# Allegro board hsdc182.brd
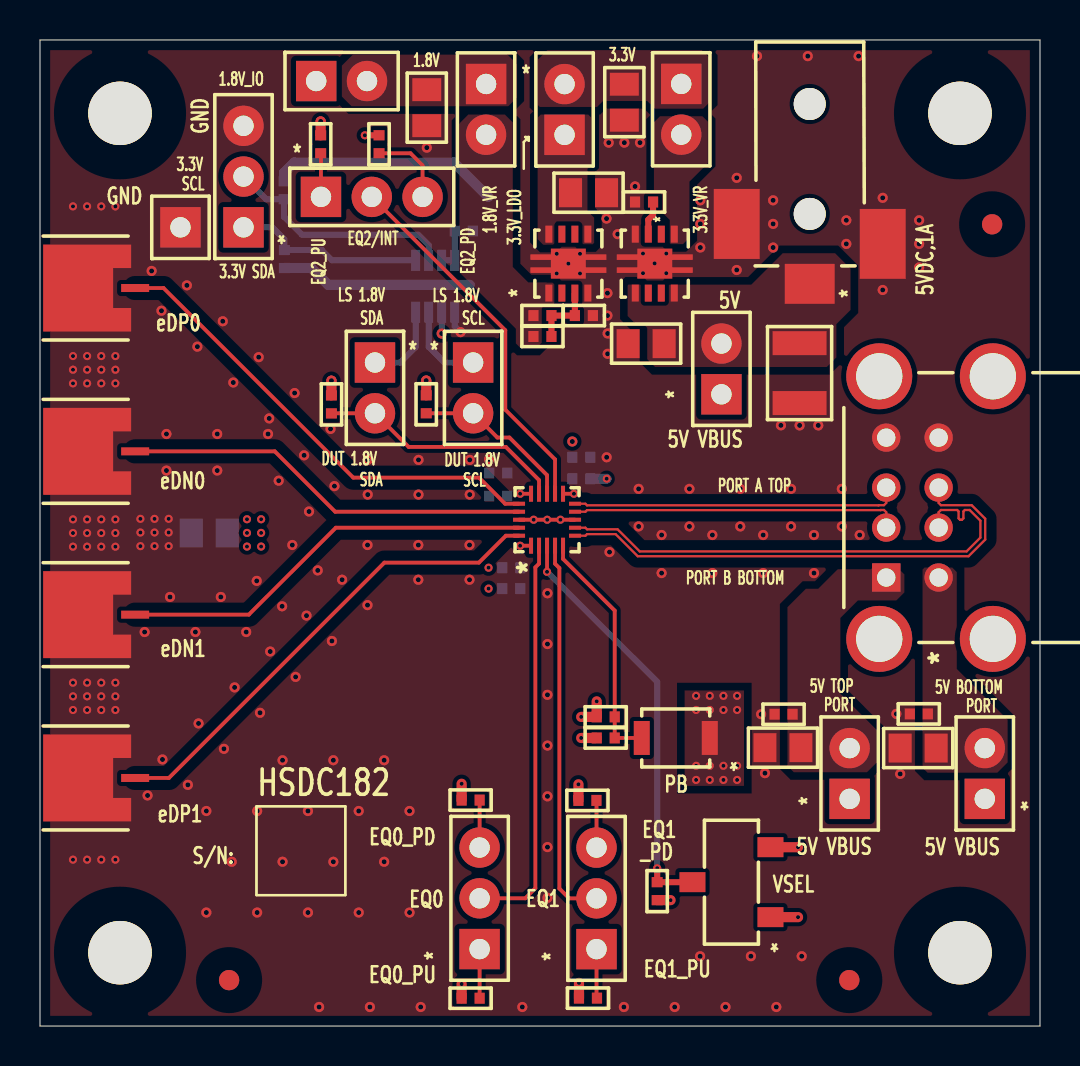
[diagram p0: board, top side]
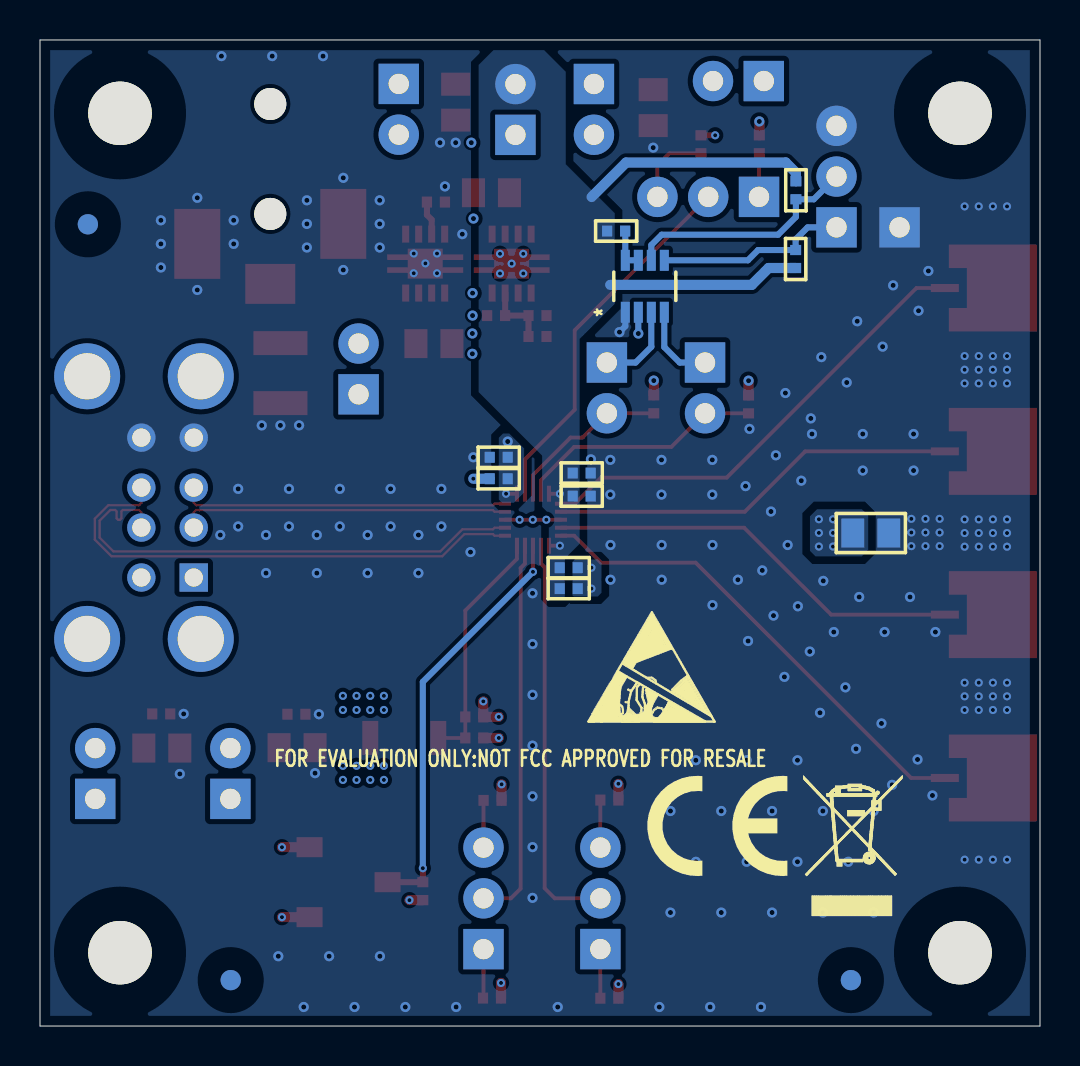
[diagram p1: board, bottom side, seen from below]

Outline 50 x 49.34 mm; copper layers: TOP, L2, L3, BOTTOM. Coordinates in mm from the lower left corner of the outline.
Outline path: 0,49.34 50,49.34 50,0 0,0 0,49.34

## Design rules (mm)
constraint set DEFAULT: min track width 0.191
net group 1.8V_IO: nets N16778222 N16778248 N16778386 N16778440 N16778562 N16778631 R_SCL R_SDA RESETB/ VIOSEL
net group CLS1: nets DNA DNB DPA DPB EDN0_1 EDN1_1 EDP0_1 EDP1_1
net group N16778948: nets N16779025

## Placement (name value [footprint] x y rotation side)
C1  47uF  [CAP_1210]  37.98 32.67 270 top
C2  .1uF  [CAP_0402]  27.07 27.39 0 bottom
C3  .1uF  [CAP_0402]  27.07 28.46 0 bottom
C4  2.2uF  [CAP_0805]  37.15 13.93 180 top
C5  .1uF  [CAP_0402]  37.18 15.6 180 top
C6  .1uF  [CAP_0402]  43.94 15.62 180 top
C7  2.2uF  [CAP_0805]  43.91 13.91 180 top
C8  .01uF  [CAP_0402]  22.92 26.52 180 bottom
C9  .01uF  [CAP_0402]  23.57 21.89 180 bottom
C10  .1uF  [CAP_0402]  22.92 27.67 180 bottom
C11  .1uF  [CAP_0402]  23.57 22.93 180 bottom
C12  .1uF  [CAP_0402]  30.86 6.75 270 top
C13  .1uF  [CAP_0402]  28.29 15.47 180 top
C14  1uF  [CAP_0805]  30.31 34.15 180 top
C15  10uF  [CAP_0805]  29.22 46.23 270 top
C16  1uF  [CAP_0805]  27.43 41.7 0 top
C17  .01uF  [CAP_0402]  25.12 34.5 0 top
C18  10uF  [CAP_0805]  19.34 45.95 270 top
C19  .01uF  [CAP_0402]  30.2 41.23 180 top
J1  DC JACK  [JACK_SMRT_PJ1-022-SMT-TR]  38.49 43.59 90 top
J2  HDR2X1  [HDR_THVT_1X2_254_871]  34.07 31.61 90 top
J3  HDR2X1  [HDR_THVT_1X2_254_871]  40.48 11.37 90 top
J4  TypeA Stacked  [USB-A_THRT_AU-Y1008-2]  47.64 25.94 90 top
J5  HDR3X1  [HDR_THVT_1X3_254_871]  27.83 3.85 90 top
J6  SMP  [CON_SMRT_19S201-40ML5]  2.81 36.93 270 top
J7  SMP  [CON_SMRT_19S201-40ML5]  2.81 28.76 270 top
J8  SMP  [CON_SMRT_19S201-40ML5]  2.81 20.58 270 top
J9  SMP  [CON_SMRT_19S201-40ML5]  2.81 12.41 270 top
J10  HDR2X1  [HDR_THVT_1X2_254_871]  47.24 11.37 90 top
J11  HDR3X1  [HDR_THVT_1X3_254_871]  21.98 3.85 90 top
J12  HDR3X1  [HDR_THVT_1X3_254_871]  14.05 41.49 0 top
J13  HDR2X1  [HDR_THVT_1X2_254_871]  13.81 47.28 0 top
J14  HDR2X1  [HDR_THVT_1X2_254_871]  32.06 47.14 270 top
J15  HDR2X1  [HDR_THVT_1X2_254_871]  26.23 44.59 90 top
J16  HDR2X1  [HDR_THVT_1X2_254_871]  22.3 47.14 270 top
J17  HDR2X1  [HDR_THVT_1X2_254_871]  16.75 33.2 270 top
J18  HDR2X1  [HDR_THVT_1X2_254_871]  21.66 33.2 270 top
J19  HDR3X1  [HDR_THVT_1X3_254_871]  10.18 39.96 90 top
NOREF  -  []  0 49.34 0 top
NOREF#2  -  [unnamed#2]  4 45.67 0 top
NOREF#3  -  [unnamed#2]  46 3.67 0 top
NOREF#4  -  []  8.59 6.2 0 top
NOREF#5  -  []  0 0 0 top
NOREF#6  -  []  -18.79 5.95 0 top
NOREF#7  -  [unnamed#2]  9.45 2.3 0 top
NOREF#8  -  [unnamed#2]  4 3.67 0 top
NOREF#9  -  [unnamed#2]  47.61 40.12 0 top
NOREF#10  -  []  4 45.67 0 top
NOREF#11  -  []  88.9 38.1 0 top
NOREF#12  -  [unnamed#2]  46 45.67 0 top
NOREF#13  -  []  50 0 90 top
NOREF#14  -  []  46 3.67 90 top
NOREF#15  -  [unnamed#2]  40.46 2.3 0 top
NOREF#16  -  []  -3.81 -69.85 0 top
NOREF#17  -  [unnamed#2]  40.46 2.3 180 bottom
NOREF#18  -  []  17.14 16.39 180 bottom
NOREF#19  -  [unnamed#2]  9.45 2.3 180 bottom
NOREF#20  -  []  16.13 10.01 180 bottom
NOREF#21  -  [unnamed#2]  47.61 40.12 180 bottom
R1  10K  [RES_0402]  27.4 1.4 0 top
R2  10K  [RES_0402]  27.37 11.29 180 top
R3  10K  [RES_0402]  21.53 1.39 0 top
R4  10K  [RES_0402]  21.53 11.31 180 top
R5  10K  [RES_0402]  14.03 44.12 270 top
R6  2.2K  [RES_0402]  28.29 14.41 0 top
R7  10K  [RES_0402]  16.95 44.12 90 top
R8  28.0K  [RES_0402]  25.12 35.55 0 top
R9  56.2K  [RES_0402]  27.19 35.55 0 top
R10  0  [RES_0805]  8.46 24.67 180 bottom
R11  200K  [RES_0402]  21.19 39.78 0 bottom
R12  1K  [RES_0402]  14.57 31.1 270 top
R13  1K  [RES_0402]  19.31 31.11 270 top
R14  4.7K  [RES_0402]  12.22 38.38 270 bottom
R15  4.7K  [RES_0402]  12.2 41.82 90 bottom
SW1  Switch  [SW_SMVT_CJS-1201B]  34.57 7.2 180 top
SW2  RESETB  [SW_SMVT_B3U-1000P]  31.79 14.41 180 top
TP1  TEST POINT  [HDR_THVT_1X1_871]  7.02 39.96 90 top
U1  TUSB2E221QFN  [VBW0020A]  25.35 25.33 90 top
U2  TPS73633 DRB  [DRB0008BA_150X175]  30.74 38.15 270 top
U3  TPS73601 DRB  [DRB0008BA_150X175]  26.42 38.15 90 top
U4  TCA39306DDFR  [DDF0008A]  19.76 37.02 90 bottom

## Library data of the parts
C1 = CAPACITOR POL: signal model: DEFAULT_CAPACITOR_4.7e+07pF_1_2
C2 C3 C5 C6 C10-C13 = CAP NP: signal model: DEFAULT_CAPACITOR_100000pF_1_2
C4 C7 = CAPACITOR POL: signal model: DEFAULT_CAPACITOR_2.2e+06pF_1_2
C8 C9 C17 C19 = CAP NP: signal model: DEFAULT_CAPACITOR_10000pF_1_2
C14 C16 = CAP NP: signal model: DEFAULT_CAPACITOR_1e+06pF_1_2
C15 C18 = CAP NP: signal model: DEFAULT_CAPACITOR_1e+07pF_1_2
J1 = PWR JACK
J2 J3 J10 J13-J18 = HDR2X1 M .1
J4 = AU-Y1008-2_0
J5 J11 J12 J19 = HDR3X1 M .1
J6-J9 = SMB_0
R1-R5 R7 = RES: signal model: DEFAULT_RESISTOR_10000OHM_1_2
R6 = RES: signal model: DEFAULT_RESISTOR_2200OHM_1_2
R8 = RES: signal model: DEFAULT_RESISTOR_28000OHM_1_2
R9 = RES: signal model: DEFAULT_RESISTOR_56200OHM_1_2
R10 = RES: signal model: DEFAULT_RESISTOR_0.001OHM_1_2
R11 = SG73P1ETTP2003D
R12 R13 = RES: signal model: DEFAULT_RESISTOR_1000.000000OHM_1_2
R14 R15 = RC0402JR-074K7L
SW1 = Switch CJS-1201
SW2 = SW KEY-SPST
TP1 = Test Point Small
U1 = TUSB2E221QFN
U2 = TPS736_DRB_3
U3 = TPS736_DRB_4
U4 = TCA39306DDFR_0

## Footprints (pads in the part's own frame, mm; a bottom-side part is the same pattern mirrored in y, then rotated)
CAP_0402
  rect 0.51x0.55 smd: 1(-0.45,0) 2(0.45,0)
CAP_0805
  rect 1.15x1.45 smd: 1(-0.9,0) 2(0.9,0)
CAP_1210
  rect 1.2x2.7 smd: 1(-1.5,0) 2(1.5,0)
CON_SMRT_19S201-40ML5
  rect 0.4x1.4 smd: 1(0,1.95)
  custom 1.088x1.088 smd: 2(0,-0.45)
DDF0008A
  rect 1.05x0.45 smd: 1(-1.3,0.975) 2(-1.3,0.325) 3(-1.3,-0.325) 4(-1.3,-0.975) 5(1.3,-0.975) 6(1.3,-0.325) 7(1.3,0.325) 8(1.3,0.975)
DRB0008BA_150X175
  rect 0.85x0.35 smd: 1(-1.475,0.975) 2(-1.475,0.325) 3(-1.475,-0.325) 4(-1.475,-0.975) 5(1.475,-0.975) 6(1.475,-0.325) 7(1.475,0.325) 8(1.475,0.975)
  custom 0.375x0.375 smd: 9(0,0)
HDR_THVT_1X1_871
  rect 2.02x2.02 hole 1.02: 1(0,0)
HDR_THVT_1X2_254_871
  rect 2.02x2.02 hole 1.02: 1(0,0)
  round 2.02 hole 1.02: 2(2.54,0)
HDR_THVT_1X3_254_871
  rect 2.02x2.02 hole 1.02: 1(0,0)
  round 2.02 hole 1.02: 2(2.54,0) 3(5.08,0)
JACK_SMRT_PJ1-022-SMT-TR
  round 1.6 hole 1.6 unplated: (-2.95,0) (2.55,0)
  rect 2x2.5 smd: 1(-6.45,0)
  rect 3.5x2.3 smd: 2(-3.45,3.65) 3(-4.45,-3.65)
RES_0402
  rect 0.51x0.55 smd: 1(-0.45,0) 2(0.45,0)
RES_0805
  rect 1.15x1.45 smd: 1(-0.9,0) 2(0.9,0)
SW_SMVT_B3U-1000P
  rect 0.8x1.7 smd: 1(-1.7,0) 2(1.7,0)
SW_SMVT_CJS-1201B
  rect 1.3x1 smd: 1(-1.95,1.75) 2(1.95,0) 3(-1.95,-1.75)
unnamed#2
  round 3.175 hole 3.175 unplated: (0,0)
USB-A_THRT_AU-Y1008-2
  rect 1.42x1.42 hole 0.914: 1(-3.5,5.33)
  round 1.42 hole 0.914: 2(-1,5.33) 3(1,5.33) 4(3.5,5.33) 5(-3.5,2.71) 6(-1,2.71) 7(1,2.71) 8(3.5,2.71)
  round 3.3 hole 2.311: 9(-6.57,0) 10(6.57,0) 11(-6.57,5.68) 12(6.57,5.68)
VBW0020A
  rect 0.8x0.2 smd: 1(-1.3,0.8) 2(-1.3,0.4) 3(-1.3,0) 4(-1.3,-0.4) 5(-1.3,-0.8) 11(1.3,-0.8) 12(1.3,-0.4) 13(1.3,0) 14(1.3,0.4) 15(1.3,0.8)
  rect 0.2x0.6 smd: 6(-0.8,-1.4) 7(-0.4,-1.4) 8(0,-1.4) 9(0.4,-1.4) 10(0.8,-1.4) 16(0.8,1.4) 17(0.4,1.4) 18(0,1.4) 19(-0.4,1.4) 20(-0.8,1.4)

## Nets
1.8V: C2.1 C3.1 C18.1 J13.2 J16.1 SW1.3 U1.11
1.8V_IO: J13.1 R1.1 R3.1 R5.1 R6.1 R12.1 R13.1 U4.2
3.3V: C8.1 C9.1 C10.1 C11.1 C15.1 J14.1 J15.2 R11.2 R14.2 R15.2 U1.1 U1.15
3.3V_LDO: C16.1 J15.1 U3.5 U3.8
5V: C1.1 C14.1 J1.1(T) J2.2 U2.5 U2.8
5V VBUS: J2.1 J3.1 J10.1
5V_J1: C4.1 C5.1 J3.2 J4.1
5V_J2: C6.1 C7.1 J4.5 J10.2
GND: C1.2 C3.2 C4.2 C5.2 C6.2 C7.2 C8.2 C10.2 C14.2 C15.2 C16.2 C18.2 C19.2 J1.2 J1.3 J4.4 J4.8 J6.2 J7.2 J8.2 J9.2 J19.3 R9.2 R10.2 TP1.1(TP) U2.4 U2.9 U3.4 U3.9 U4.1
GND_SIGNAL: C2.2 C9.2 C11.2 C12.2 C13.2 R2.2 R4.2 R7.2 R10.1 SW1.1 SW2.1 U1.8 U1.18
DNA: J4.2 U1.9
DNB: J4.6 U1.7
DPA: J4.3 U1.10
DPB: J4.7 U1.6
EDN0_1: J7.1(CENTER) U1.17
EDN1_1: J8.1(CENTER) U1.19
EDP0_1: J6.1(CENTER) U1.16
EDP1_1: J9.1(CENTER) U1.20
EQ0: J11.2 U1.2
EQ1: J5.2 U1.4
EQ2/INT: J12.2 U1.12
R_SCL: J18.2 R13.2 U1.13
R_SDA: J17.2 R12.2 U1.14
RESETB/: C13.1 R6.2 SW2.2 U1.5
VIOSEL: C12.1 SW1.2 U1.3(VIOSEL)
N16778222: J5.1 R1.2
N16778248: J5.3 R2.1
N16778386: J11.1 R3.2
N16778440: J11.3 R4.1
N16778562: J12.1 R5.2
N16778631: J12.3 R7.1
N16778928: J14.2 U2.1(VOUT)
N16778948: C17.1 J16.2 R8.1 U3.1(VOUT)
N16779019: C19.1 U2.3
N16779025: C17.2 R8.2 R9.1 U3.3
N16794481: J17.1 U4.4
N16794484: J18.1 U4.3
N16794750: R11.1 U4.7(VREF2) U4.8
N16794768: J19.1 R14.1 U4.5
N16794775: J19.2 R15.1 U4.6

Pads without a net: J4 9 10 11 12; U2 2 6 7; U3 2 6 7

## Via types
v1: diameter 0.406, hole 0.203, TOP to BOTTOM, 107 vias
v2: diameter 0.508, hole 0.254, TOP to BOTTOM, 151 vias

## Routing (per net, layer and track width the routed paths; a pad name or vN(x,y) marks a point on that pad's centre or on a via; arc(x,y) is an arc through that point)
1.8V: length 1.9
  TOP w0.191: U1.11 v1(26.7,26.63)
  TOP w0.508: SW1.3 v1(37.9,8.95)
  vias: v2(26.62,29.25)
1.8V_IO: length 5.5
  TOP w0.508: R6.1 v1(27.06,14.41) ; R13.1 v2(19.31,32.3) ; R1.1 v1(26.95,2.16) ; R12.1 v2(14.57,32.29) ; R3.1 v1(21.08,2.1) ; R5.1 v2(14.03,45.26)
  BOTTOM w0.305: U4.2 v2(20.08,34.65)
3.3V: length 22.3
  TOP w0.191: U1.15 v1(24.01,26.63) ; U1.1 v1(24.01,24.03)
  BOTTOM w0.508: 22.42,41.48 20.69,43.21 12.71,43.21 12.2,42.7 R15.2 ; R14.2 13.57,37.93 14.41,37.09 21.49,37.09
GND: length 1.1
  TOP w0.191: 2.36,36.93 J6.2
  BOTTOM w0.305: U4.1 20.73,35.01 v2(21.03,34.72)
  vias: v1(1.65,41.01) v1(1.65,33.52) v1(1.65,32.84) v1(1.65,32.16) v1(1.65,25.35) v1(1.65,24.67) v1(1.65,23.98) v1(1.65,17.18) v1(1.65,16.5) v1(1.65,15.81) v1(1.65,8.32) v1(2.36,41.01) v1(2.36,33.52) v1(2.36,32.84) v1(2.36,32.16) v1(2.36,25.35) v1(2.36,24.67) v1(2.36,23.98) v1(2.36,17.18) v1(2.36,16.5) v1(2.36,15.81) v1(2.36,8.32) v1(3.06,41.01) v1(3.06,33.52) v1(3.06,32.84) v1(3.06,32.16) v1(3.06,25.35) v1(3.06,24.67) v1(3.06,23.98) v1(3.06,17.18) v1(3.06,16.5) v1(3.06,15.81) v1(3.06,8.32) v1(3.77,41.01) v1(3.77,33.52) v1(3.77,32.84) v1(3.77,32.16) v1(3.77,25.35) v1(3.77,24.67) v1(3.77,23.98) v1(3.77,17.18) v1(3.77,16.5) v1(3.77,15.81) v1(3.77,8.32) v1(5.02,25.38) v1(5.02,24.69) v1(5.02,24.01) v1(5.73,25.38) v1(5.73,24.69) v1(5.73,24.01) v1(6.43,25.38) v1(6.43,24.69) v1(6.43,24.01) v1(25.84,38.64) v1(25.84,37.66) v1(26.42,38.15) v1(27,38.64) v1(27,37.66) v1(30.15,38.65) v1(30.15,37.67) v1(30.73,38.16) v1(31.31,38.65) v1(31.31,37.67) v2(5.23,19.72) v2(5.38,11.54) v2(5.58,37.78) v2(6.07,35.79) v2(6.12,13.34) v2(6.32,29.62) v2(6.32,27.8) v2(6.5,21.47) v2(7.34,37.06) v2(7.39,12.07) v2(7.77,19.72) v2(7.87,34) v2(7.93,15.14) v2(8.32,10.76) v2(8.32,5.68) v2(8.86,29.62) v2(8.86,27.8) v2(9.04,21.47) v2(9.14,35.27) v2(9.2,13.87) v2(9.59,8.22) v2(9.66,32.2) v2(9.73,16.94) v2(10.31,19.72) v2(10.84,22.27) v2(10.93,33.47) v2(10.86,10.76) v2(10.86,5.68) v2(11,15.67) v2(11.4,29.62) v2(11.46,30.4) v2(11.51,18.74) v2(11.94,27.29) v2(12.11,21) v2(12.13,13.3) v2(12.13,8.22) v2(12.62,24.07) v2(12.73,31.67) v2(12.78,17.47) v2(13.21,28.56) v2(13.33,20.54) v2(13.4,10.76) v2(13.4,5.68) v2(13.45,25.75) v2(13.89,22.8) v2(13.95,0.95) v2(14.53,29.88) v2(14.6,19.27) v2(14.72,27.02) v2(14.67,13.3) v2(14.67,8.22) v2(15.11,22.33) v2(15.94,10.76) v2(15.94,5.68) v2(16.39,28.33) v2(16.39,26.59) v2(16.38,24.07) v2(16.38,21.06) v2(16.49,0.95) v2(17.21,13.3) v2(17.21,8.22) v2(18.48,10.76) v2(18.48,5.68) v2(18.93,28.33) v2(18.93,26.59) v2(18.92,24.07) v2(18.92,22.33) v2(19.03,0.95) v2(19.34,43.95) v2(21.49,28.33) v2(21.49,26.59) v2(21.48,24.07) v2(21.48,22.33) v2(22.45,28.36) v2(24.11,0.95) v2(25.37,21.65) v2(25.37,19.11) v2(25.37,16.57) v2(25.37,14.03) v2(25.37,11.49) v2(25.37,8.95) v2(25.37,6.41) v2(28.33,40.4) v2(28.33,28.46) v2(28.44,44.2) v2(28.37,36.67) v2(28.37,35.55) v2(28.38,34.65) v2(28.38,33.64) v2(28.48,23.72) v2(28.89,39.62) v2(29.22,44.2) v2(29.19,0.95) v2(29.75,42.01) v2(29.93,26.88) v2(29.93,25) v2(30,44.2) v2(31.08,24.57) v2(31.08,22.66) v2(31.73,0.95) v2(32.47,26.88) v2(32.47,25) v2(33.02,41.32) v2(33.02,40.14) v2(33.02,38.95) v2(33,3.49) v2(33.62,24.57) v2(33.62,22.66) v2(34.27,0.95) v2(34.84,42.44) v2(34.84,37.83) v2(35.01,26.88) v2(35.01,25) v2(35.54,3.49) v2(35.85,48.53) v2(36.06,15.6) v2(36.16,24.57) v2(36.16,22.66) v2(36.25,12.65) v2(36.66,41.32) v2(36.66,40.14) v2(36.66,38.95) v2(36.81,0.95) v2(37.05,30.06) v2(37.55,26.88) v2(37.55,25) v2(37.98,30.05) v2(38.08,3.49) v2(38.39,48.53) v2(38.7,24.57) v2(38.7,22.66) v2(38.91,30.05) v2(40.09,26.88) v2(40.09,25) v2(40.32,40.32) v2(40.32,39.14) v2(40.93,48.53) v2(40.99,24.57) v2(42.14,41.44) v2(42.14,36.83) v2(42.82,15.62) v2(43.01,12.61) v2(43.96,40.32) v2(43.96,39.14) v2(43.96,37.95)
GND_SIGNAL: length 9.6
  TOP w0.191: U1.8 v1(26.02,25.33) v1(25.36,25.33) v1(24.68,25.33) U1.18
  TOP w0.305: R7.2 v1(16.24,44.57)
  TOP w0.508: SW1.1 v1(37.9,5.45) ; C12.2 v1(31.53,6.3) ; v1(27.84,16.25) C13.2 v1(27.06,15.47) ; R4.2 v1(21.08,12.12) ; R2.2 v1(26.92,12.1)
  BOTTOM w0.508: C2.2 v1(28.33,27.39)
  vias: v1(10.35,25.36) v1(10.35,24.67) v1(10.35,23.99) v1(11.06,25.36) v1(11.06,24.67) v1(11.06,23.99) v1(22.43,22.93) v1(22.43,21.89) v1(32.81,16.52) v1(32.81,15.82) v1(32.81,13.02) v1(32.81,12.31) v1(33.49,16.52) v1(33.49,15.82) v1(33.49,13.02) v1(33.49,12.31) v1(34.17,16.52) v1(34.17,15.82) v1(34.17,13.02) v1(34.17,12.31) v1(34.85,16.52) v1(34.85,15.82) v1(34.85,13.02) v1(34.85,12.31)
DNA: length 16.4
  TOP w0.114: J4.2 42.31,25.71 42.2,25.82 42.04,25.82 42.03,25.81 27.35,25.81 27.27,25.73 U1.9
DNB: length 25.8
  TOP w0.114: J4.6 44.93,25.71 45.05,25.82 45.86,25.82 45.93,25.75 45.93,25.4 46,25.33 46.1,25.33 46.17,25.4 46.17,25.75 46.24,25.82 46.48,25.82 47.02,25.28 47.02,24.44 46.33,23.75 29.98,23.75 28.88,24.85 27.35,24.85 27.27,24.93 U1.7
DPA: length 16.4
  TOP w0.114: U1.10 27.27,26.13 27.35,26.05 41.93,26.05 41.94,26.06 42.2,26.06 42.31,26.18 J4.3
DPB: length 25.8
  TOP w0.114: U1.6 27.27,24.53 27.35,24.61 28.78,24.61 29.88,23.51 46.43,23.51 47.26,24.34 47.26,25.38 46.58,26.06 45.05,26.06 44.93,26.18 J4.7
EDN0_1: length 20.4
  TOP w0.191: U1.17 14.76,25.73 11.74,28.76 J7.1
EDN1_1: length 21
  TOP w0.191: J8.1 10.44,20.58 14.79,24.93 U1.19
EDP0_1: length 23.7
  TOP w0.191: J6.1 6.18,36.93 15.66,27.44 21.95,27.44 23.26,26.13 U1.16
EDP1_1: length 24.2
  TOP w0.191: U1.20 23.29,24.53 21.95,23.19 17.22,23.19 6.44,12.41 J9.1
EQ0: length 20.2
  TOP w0.191: J11.2 24.26,6.39 24.77,6.9 24.77,22.95 24.95,23.14 U1.2
EQ1: length 19.3
  TOP w0.191: U1.4 25.75,23.13 25.97,22.92 25.97,6.88 26.46,6.39 J5.2
EQ2/INT: length 18.6
  TOP w0.191: U1.12 25.75,28.35 23.26,30.84 23.26,34.81 J12.2
R_SCL: length 8.3
  TOP w0.191: R13.2 J18.2 22.87,29.45 23.47,29.45 25.35,27.57 U1.13
R_SDA: length 12.4
  TOP w0.191: R12.2 14.58,30.66 J17.2 18.43,28.98 23.29,28.98 24.95,27.32 U1.14
RESETB/: length 12
  TOP w0.191: SW2.2 R6.2 C13.1 28.74,20.79 26.15,23.37 U1.5
VIOSEL: length 20.9
  TOP w0.191: U1.3 v1(25.35,22.73)
  TOP w0.305: v1(30.86,7.9) C12.1 SW1.2
  BOTTOM w0.305: v1(30.86,7.9) 30.86,17.22 v1(25.35,22.73)
N16778222: length 2.5
  TOP w0.191: J5.1 27.83,1.42 R1.2
N16778248: length 2.4
  TOP w0.191: R2.1 27.83,11.29 J5.3
N16778386: length 2.5
  TOP w0.191: J11.1 R3.2
N16778440: length 2.4
  TOP w0.191: J11.3 R4.1
N16778562: length 2.2
  TOP w0.191: R5.2 14.05,43.65 J12.1
N16778631: length 4
  TOP w0.191: J12.3 19.13,43.07 18.52,43.67 R7.1
N16779019: length 1.7
  TOP w0.305: U2.3 30.41,40.35 30.65,40.58 C19.1
N16779025: length 3.3
  TOP w0.305: C17.2 R8.2 R9.1 U3.3
N16794481: length 4.1
  BOTTOM w0.305: J17.1 18.01,33.2 18.78,33.97 U4.4
N16794484: length 4.3
  BOTTOM w0.305: J18.1 20.22,33.2 19.43,33.99 U4.3
N16794750: length 2.1
  BOTTOM w0.305: R11.1 20.73,39.77 U4.8 U4.7
N16794768: length 9.6
  BOTTOM w0.305: U4.5 14.61,38.32 14.09,38.83 R14.1 12.22,39.36 11.62,39.96 J19.1
N16794775: length 12
  BOTTOM w0.305: J19.2 11.31,41.37 R15.1 12.2,40.49 13.1,39.6 18.92,39.6 19.43,39.08 U4.6

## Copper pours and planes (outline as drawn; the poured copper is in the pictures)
1.8V on TOP: 23.41,46.02 15.58,46.02 15.1,46.5 15.1,48.06 15.64,48.61 23.38,48.61 23.82,48.16 23.82,46.44
1.8V on BOTTOM: 27.06,26.34 27.06,29.44 26.85,29.65 26.41,29.65 25.79,29.03 25.79,26.7 26.31,26.18 26.9,26.18
1.8V on L3: 15.09,47.98 15.09,41.92 22.08,34.93 22.08,24.06 30.14,16 30.14,10.06 32.09,8.12 37.68,8.12 38.27,8.71 38.27,9.34 37.29,10.32 37.29,21.72 30.17,28.84 30.17,40.92 27.79,43.3 21.78,43.3 21.06,44.02 21.06,47.54 19.88,48.71 15.82,48.71
1.8V_IO on L3: 9.9,48.77 8.13,47 8.13,6.02 12.35,1.8 28.86,1.8 29.65,2.58 29.65,15.8 21.48,23.96 21.48,34.7 14.94,41.24 14.94,47.97 14.15,48.77
3.3V on TOP: 25.37,48.83 33.09,48.83 33.49,48.43 33.49,46.24 33.16,45.9 30.74,45.9 30.36,46.29 28.15,46.29 27.85,45.99 24.99,45.99 24.86,46.12 24.86,48.32
3.3V on BOTTOM: 24.8,48.83 27.32,48.83 28.07,48.09 28.07,31.72 24.89,28.54 24.89,25.98 24.56,25.64 24.56,21.49 24.42,21.35 23.89,21.35 23.76,21.48 23.76,23.39 23.02,24.13 23.02,34.38 21.26,36.13 21.26,40.67 23.71,43.12 23.71,47.75
3.3V_LDO on TOP: 24.88,45.45 24.88,39.37 25.16,39.09 25.65,39.09 25.75,39.2 25.75,40.18 25.84,40.27 26.95,40.27 27.06,40.16 27.06,39.23 27.17,39.12 27.64,39.12 27.71,39.19 27.71,40.45 27.37,40.78 27.37,42.89 27.57,43.09 27.57,45.45 27.27,45.75 25.18,45.75
5V on TOP: 40.53,37.89 40.53,35.83 39.82,35.13 39.82,33.46 39.34,32.98 30.75,32.98 30.36,33.37 30.36,34.93 30.17,35.12 29.79,35.12 29.38,35.53 29.38,37.06 29.43,37.1 30.01,37.1 30.06,37.05 30.06,36.17 30.19,36.05 31.31,36.05 31.41,36.15 31.41,37.03 31.48,37.1 35.56,37.1 37.14,38.67 39.75,38.67
5V VBUS on L3: 31.89,43.14 48.82,43.14 49.49,42.47 49.49,9.33 48.28,8.12 40.03,8.12 37.74,10.41 37.74,21.98 30.68,29.04 30.68,41.93
5V_J1 on TOP: 41.35,12.7 37.69,12.7 37.37,13.02 37.37,20.96 38.29,21.88 38.91,21.88 39.89,22.85 41.54,22.85 41.69,23 42.82,23 43.22,22.6 43.22,21.7 42.81,21.29 40.89,21.29 40.02,20.42 40.02,16.63 41.82,14.83 41.82,13.17
5V_J2 on TOP: 47.87,12.68 44.38,12.68 44.13,12.93 44.13,22.84 44.44,23.15 45.4,23.15 45.84,22.72 45.84,17.87 48.38,15.33 48.38,13.19
GND on TOP: 0.51,48.83 49.49,48.83 49.49,0.51 0.51,0.51 ; 4 cut-outs
GND on BOTTOM, L3: 0.51,48.83 49.49,48.83 49.49,0.51 0.51,0.51
GND on L2: 20.91,48.83 49.49,48.83 49.49,28.41 32.24,28.41 20.91,39.74
GND_SIGNAL on TOP: 32.23,16.79 32.23,12.02 35.2,12.02 35.2,16.79
GND_SIGNAL on BOTTOM: 23.45,21.63 23.45,23.24 23.35,23.35 22.09,23.35 21.93,23.18 21.93,21.67 22.11,21.49 23.32,21.49
GND_SIGNAL on BOTTOM: 8.59,25.54 8.59,23.82 8.91,23.5 11.23,23.5 11.5,23.77 11.5,25.51 11.15,25.86 8.91,25.86
GND_SIGNAL on L2: 0.51,48.83 20.56,48.83 20.56,39.54 32.09,28.01 49.49,28.01 49.49,0.51 0.51,0.51
N16778928 on TOP: 31.49,39.17 31.49,40.33 30.7,41.12 30.7,45.22 31.11,45.64 33.01,45.64 33.39,45.25 33.39,43.17 32.47,42.25 32.47,39.45 32.15,39.12 31.54,39.12
N16778948 on TOP: 23.24,45.61 21.42,45.61 20.97,45.16 20.97,37.71 23.79,34.89 23.79,34.15 24.01,33.94 24.83,33.94 25.09,34.2 25.09,35.91 25.23,36.06 25.61,36.06 25.74,36.19 25.74,37.09 25.62,37.21 24.41,37.21 23.64,37.98 23.64,45.22

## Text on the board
BOTTOM: LAYER 4 - BOTTOM SIDE
Board Geometry/Soldermask Bottom: SOLDERMASK BOTTOM
Package Geometry/Pastemask Bottom: PASTEMASK BOTTOM
Ref Des/Silkscreen Bottom: FOR EVALUATION ONLY:NOT FCC APPROVED FOR RESALE | SILKSCREEN BOTTOM
User.Comments: PLANO, TX 75074 | 3060 SUMMIT AVE. | FAX: (972) 424-3882 | PHONE: (972) 424-3880 | KRYPTON SOLUTIONS LLC. | WWW.KRYPTON-SOLUTIONS.COM
TOP: LAYER 1 - TOP SIDE
Board Geometry/Soldermask Top: SOLDERMASK TOP
Package Geometry/Pastemask Top: PASTEMASK TOP
Ref Des/Silkscreen Top: DUT 1.8V | LS 1.8V | SDA | SCL | PORT B BOTTOM | PORT A TOP | 5V TOP | PORT | 5V BOTTOM | 3.3V | 1.8V_IO | 3.3V SDA | EQ2/INT | 1.8V | EQ2_PU | EQ2_PD | 1.8V_VR | 3.3V_LDO | 3.3V_VR | GND | eDP0 | eDP1 | eDN0 | eDN1 | PB | 5V VBUS | 5V | EQ0_PD | EQ0_PU | EQ0 | EQ1 | _PD | EQ1_PU | VSEL | 5VDC,1A | HSDC182 | SILKSCREEN TOP
L2: LAYER 2 - GND PLANE
L3: LAYER 3 - PWR PLANE
XSECTION_CHART: *  SURFACE - AIR 0 MIL | *  DIELECTRIC - SOLDERMASK-0.8MIL 0.8 MIL | L1 TOP CONDUCTOR - COPPER_1/2OZ_PLATED 1.4 MIL | *  DIELECTRIC - FILL_0.100 3.94 MIL | L2 L2 PLANE - COPPER_1.0OZ 1.4 MIL | *  DIELECTRIC - CORE_1.1214 44.15 MIL | L3 L3 PLANE - COPPER_1.0OZ 1.4 MIL | L4 BOTTOM CONDUCTOR - COPPER_1/2OZ_PLATED 1.4 MIL | DESIGN CROSS SECTION CHART | ___________________________ | TOTAL THICKNESS 59.23 MIL | 1-4
DIMENSION: FABRICATION DRAWING | CAD ORIGIN
User.10: LAYER 1 | LAYER 2 | LAYER 3 | LAYER 4 | LAYER | NO. | TABLE 1: | TOP | L2 | L3 | BOTTOM | NAME | DIFFIRENTIAL PAIR | IMPEDANCE (OHMS) | 90  +/- 10% | DIFF TRACE | WIDTH | 0.0045" | SPACING | 0.005" | SINGLE ENDED | 42.5 +/- 5% | TRACE WIDTH | 0.0075" | REFERENCE | SPECIAL FAB NOTES: | PLACE DRILL CHART HERE: | 1:FAB SHOP MUST FOLLOW THE SOLDER MASK REVIEW LAYERS. | 2: | Single Ended Impedance of 45 ohms is optimal but cannot go above 45 ohms. | MIN. ANNULAR RING 2 MIL EXTERNAL PER IPC-6012C CLASS 2 | REGISTRATION TOLERANCES: METAL +/- X MIL,HOLES +/- X MIL | IMPEDANCE CONTROL: | BOARD SIZE (REFER ALSO ARRAY/PANEL PROFILING INFORMATION) | MIXED DIELECTRIC: | LAMINATE MATERIAL: | THICKNESS: | TOLERANCE: | COPPER THICKNESS (FINISHED): | BOARD FINISH: | NUMBER OF LAYERS: | MIN. TRACK WIDTH: | MIN. CLEARANCE  : | MIN. VIA PAD/DRILL: | THIEVING ALLOWED: | X | OUTER: | INNER SIGNAL: | INNER PLANE: | OTHER: | SILKSCREEN: | SOLDERMASK: (PER IPC-6011,6012) | BOARD SURFACE TREATMENT: | ADDITIONAL REQUIREMENTS: | VENDOR MARKING: | SILKSCREEN COLOR: | SOLDERMASK COLOR: | THROUGH-HOLE VIA TREATMENT: | VIA FILL USING NON-CONDUCTIVE EPOXY: | FOR WIRE BONDING: | VENDOR DATE CODE,UL,LOGO: | FR-4 HIGH Tg | 0.062" +/-10% | IPC-6012C TYPE 3 CLASS 2 | OTHER +/- | MICRO-SECTION | CERTIFICATES OF COMPLIANCE | NICKEL/GOLD (ENIG) | IMMERSION TIN | HARD GOLD | IN AN OPEN AREA | 1/4 OZ. | NO | PER GERBER | 4 | 4.5 MIL | 4 MIL | 08/04 MIL | NONE | DESIGN INFORMATION | ROGERS 4350B | 0.093" +/-10% | YES | TDR REPORTS/COUPONS | WHITE | GREEN | SOFT GOLD | 1/2 OZ. | BOW & TWIST: | ORGANIC (OSP) | OTHER | WHERE INDICATED (SEE DRAWING) | YES - SEE TABLE 1 | ETCH | IDENTIFIER: | BLUE | RoHS | 1.0 OZ. | SILKSCREEN | PER SUPPLIED ARTWORK | ELECTRICAL TEST | UL 94V-0 | HASL | 2.0 OZ. | BREAK-AWAY | ENEPIG
User.11: ASSEMBLY TOP
User.12: ASSEMBLY BOTTOM
User.20: FIGURE | FINISHED_SIZE | 8.0 | 10.0 | 36.0 | 40.157 | 91.0 | 62.992 | 125.0 | DRILL CHART: TOP to BOTTOM | ALL UNITS ARE IN MILS | TOLERANCE_DRILL | +3.0/-3.0 | +2.0/-2.0 | PLATED | NON-PLATED | QTY | 107 | 151 | 8 | 31 | 4 | 2
